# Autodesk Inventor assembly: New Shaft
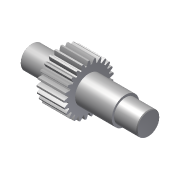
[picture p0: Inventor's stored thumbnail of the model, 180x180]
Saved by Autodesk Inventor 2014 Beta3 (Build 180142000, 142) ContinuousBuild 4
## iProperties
Created: 2011-01
Part Number: New Shaft
Document SubType Name: Assembly
Designer: Beta-8540w
ClientObjectVersion: 1
Author: Beta-8540w
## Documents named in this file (2)
- C:\Inventor 2014 Essentials\Assemblies\Chapter 09\Design Accelerators\Shaft c09-05.iam
- C:\Inventor 2014 Essentials\Assemblies\Chapter 09\Design Accelerators\Shaft c09-05.ipt
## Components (1 placed, 1 different names)
1. New Shaft:1
